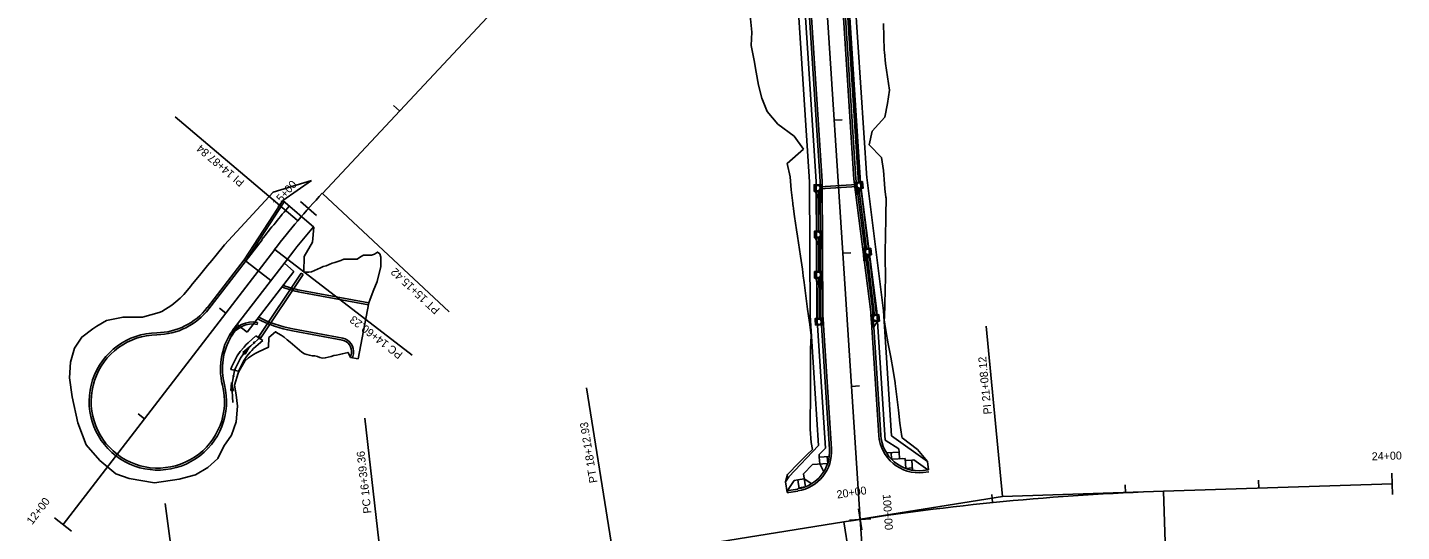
# Model space of a CAD drawing. Extents: x 979959 to 994833, y 1835619 to 1845316.
# Drawn here: x 982028 to 983058, y 1842647 to 1843025 of the extents above; entities that cross this region are included whole.
import ezdxf

# ---------------------------------------------------------------- set-up
doc = ezdxf.new("R2010")
doc.units = 0
for name, color, linetype in [('R_Drainage', 7, 'Continuous'), ('R_Horz Alg', 7, 'Continuous'), ('R_Horz Alg Annot', 7, 'Continuous'), ('R_Horz Alg Annot_Side Road', 7, 'Continuous'), ('R_Horz Alg Stationing', 7, 'Continuous'), ('R_Horz Alg Stationing_Side Road', 7, 'Continuous'), ('R_Proposed Const Limits', 7, 'Continuous'), ('R_Proposed Road', 7, 'Continuous'), ('R_Special Ditch', 7, 'Continuous')]:
    doc.layers.add(name, color=color, linetype=linetype)

msp = doc.modelspace()

# ---------------------------------------------------------------- linework, layer by layer
at = {"layer": 'R_Drainage'}
for p, q in [((982651.3, 1842908.5), (982637.8, 1843118.6)), ((982652.8, 1842908.6), (982639.3, 1843118.7)), ((982618.1, 1842902.1), (982618.1, 1842907.1)), ((982622.7, 1842894.2), (982618.3, 1842903.6)), ((982620, 1842871.5), (982619.9, 1842902.8)), ((982621.5, 1842871.5), (982621.4, 1842902.8)), ((982622.4, 1842905.5), (982650.2, 1842907.3)), ((982622.5, 1842904), (982650.3, 1842905.9)), ((982623.2, 1842894.2), (982623.1, 1842907.2)), ((982649.4, 1842908.9), (982650.5, 1842900)), ((982651, 1842900), (982654.3, 1842905.4)), ((982657.4, 1842858.6), (982651.6, 1842904.8)), ((982658.9, 1842858.8), (982653.1, 1842905)), ((982654.3, 1842909.5), (982654.9, 1842904.6)), ((982618.3, 1842867.2), (982618.3, 1842872.2)), ((982623.4, 1842859.2), (982623.3, 1842872.2)), ((982622.9, 1842859.2), (982618.5, 1842868.6)), ((982620.2, 1842841.4), (982620.1, 1842867.8)), ((982621.7, 1842841.4), (982621.6, 1842867.8)), ((982655.8, 1842859.2), (982656.3, 1842850.3)), ((982656.8, 1842850.3), (982660.5, 1842855.5)), ((982663.4, 1842808.9), (982657.9, 1842855)), ((982664.9, 1842809.1), (982659.4, 1842855.1)), ((982660.7, 1842859.6), (982661.1, 1842854.6)), ((982201.4, 1842792.6), (982233.5, 1842840.9)), ((982235.2, 1842839.8), (982233.5, 1842840.9)), ((982618.5, 1842837), (982618.4, 1842842)), ((982623.5, 1842829.1), (982623.4, 1842842.1)), ((982203, 1842791.5), (982235.2, 1842839.8)), ((982623, 1842829.1), (982618.7, 1842838.5)), ((982620.7, 1842806.2), (982620.2, 1842837.7)), ((982622.2, 1842806.2), (982621.7, 1842837.7)), ((982661.7, 1842809.5), (982662.3, 1842800.5)), ((982666.7, 1842809.8), (982667, 1842804.9)), ((982619.1, 1842801.7), (982618.8, 1842806.7)), ((982662.8, 1842800.6), (982666.4, 1842805.8)), ((982203, 1842791.5), (982201.4, 1842792.6))]:
    msp.add_line(p, q, dxfattribs=at)
for points in [[(982618.1, 1842902.1), (982618.1, 1842907.1), (982623.1, 1842907.2), (982623.1, 1842902.2)], [(982622.7, 1842894.2), (982622.6, 1842907.2), (982624.1, 1842907.2), (982624.2, 1842894.2)], [(982649.8, 1842909), (982651, 1842900), (982649.5, 1842899.8), (982648.4, 1842908.8)], [(982654.3, 1842909.5), (982654.9, 1842904.6), (982650, 1842903.9), (982649.4, 1842908.9)], [(982618.3, 1842867.2), (982618.3, 1842872.2), (982623.3, 1842872.2), (982623.3, 1842867.2)], [(982622.9, 1842859.2), (982622.8, 1842872.2), (982624.3, 1842872.2), (982624.4, 1842859.2)], [(982656.3, 1842859.3), (982656.8, 1842850.3), (982655.3, 1842850.2), (982654.8, 1842859.2)], [(982660.7, 1842859.6), (982661.1, 1842854.6), (982656.1, 1842854.2), (982655.8, 1842859.2)], [(982618.5, 1842837), (982618.4, 1842842), (982623.4, 1842842.1), (982623.5, 1842837.1)], [(982623, 1842829.1), (982622.9, 1842842.1), (982624.4, 1842842.1), (982624.5, 1842829.1)], [(982662.2, 1842809.6), (982662.8, 1842800.6), (982661.3, 1842800.5), (982660.7, 1842809.5)], [(982666.7, 1842809.8), (982667, 1842804.9), (982662, 1842804.5), (982661.7, 1842809.5)], [(982619.1, 1842801.7), (982618.8, 1842806.7), (982623.8, 1842807), (982624.1, 1842802.1)], [(982623.6, 1842802), (982623.3, 1842807), (982624.8, 1842807.1), (982625.1, 1842802.1)]]:
    msp.add_lwpolyline(points, close=True, dxfattribs=at)
for centre, radius in [((982620.6, 1842904.7), 2.5), ((982620.6, 1842904.7), 2.5), ((982620.6, 1842904.7), 2), ((982620.6, 1842904.7), 2), ((982652.1, 1842906.7), 2.5), ((982652.1, 1842906.7), 2.5), ((982652.1, 1842906.7), 2), ((982652.1, 1842906.7), 2), ((982620.8, 1842869.7), 2.5), ((982620.8, 1842869.7), 2.5), ((982620.8, 1842869.7), 2), ((982620.8, 1842869.7), 2), ((982658.4, 1842856.9), 2.5), ((982658.4, 1842856.9), 2.5), ((982658.4, 1842856.9), 2), ((982658.4, 1842856.9), 2), ((982621, 1842839.5), 2.5), ((982621, 1842839.5), 2.5), ((982621, 1842839.5), 2), ((982621, 1842839.5), 2), ((982664.4, 1842807.2), 2.5), ((982664.4, 1842807.2), 2.5), ((982664.4, 1842807.2), 2), ((982664.4, 1842807.2), 2), ((982621.5, 1842804.4), 2.5), ((982621.5, 1842804.4), 2.5), ((982621.5, 1842804.4), 2), ((982621.5, 1842804.4), 2)]:
    msp.add_circle(centre, radius, dxfattribs=at)
at = {"layer": 'R_Horz Alg'}
for p, q in [((982249.5, 1842900.7), (982462.4, 1843128.4)), ((982622.6, 1843116.2), (982652.7, 1842656.1)), ((982055.2, 1842652.3), (982213.8, 1842858.6)), ((982880, 1842677.2), (983051.5, 1842682.9)), ((982652.7, 1842656.1), (982665.3, 1842462.2)), ((982468, 1842626.5), (982640.3, 1842654.2))]:
    msp.add_line(p, q, dxfattribs=at)
for centre, radius, start, end in [((982668, 1842509.4), 573, 136.9251, 142.4445), ((982942.7, 1840768.4), 1909.9, 91.8826, 99.1106)]:
    msp.add_arc(centre, radius, start, end, dxfattribs=at)
at = {"layer": 'R_Horz Alg Annot'}
for points in [[(982230.6, 1842880.5), (982139.1, 1842958.1)], [(982249.5, 1842900.7), (982344.5, 1842811.9)], [(982213.8, 1842858.6), (982316.9, 1842779.4)]]:
    msp.add_lwpolyline(points, dxfattribs=at)
at = {"layer": 'R_Horz Alg Annot_Side Road'}
for p, q in [((982759.4, 1842673.3), (982880, 1842677.2)), ((982640.3, 1842654.2), (982759.4, 1842673.3))]:
    msp.add_line(p, q, dxfattribs=at)
for points in [[(982759.4, 1842673.3), (982747.1, 1842801.1)], [(982468, 1842626.5), (982447.4, 1842754.9)], [(982296, 1842602.9), (982281.3, 1842732.1)], [(982880, 1842677.2), (982884.3, 1842547.3)], [(982142.8, 1842585.5), (982131.7, 1842668.1)], [(982640.3, 1842654.2), (982651.6, 1842583.8)]]:
    msp.add_lwpolyline(points, dxfattribs=at)
at = {"layer": 'R_Horz Alg Stationing'}
for points in [[(982302.9, 1842966.6), (982307.3, 1842962.5)], [(982639.1, 1842955.9), (982633.1, 1842955.5)], [(982233.1, 1842894.6), (982245.1, 1842884)], [(982645.6, 1842856.1), (982639.6, 1842855.7)], [(982172.3, 1842814.5), (982177.1, 1842810.9)], [(982652.2, 1842756.3), (982646.2, 1842755.9)], [(982111.4, 1842735.2), (982116.1, 1842731.6)], [(983051.2, 1842690.9), (983051.7, 1842674.9)], [(982048.8, 1842657.2), (982061.5, 1842647.4)], [(982660.7, 1842656.6), (982644.7, 1842655.6)], [(982651.5, 1842664), (982653.9, 1842648.2)]]:
    msp.add_lwpolyline(points, dxfattribs=at)
at = {"layer": 'R_Horz Alg Stationing_Side Road'}
for points in [[(982951.3, 1842685.6), (982951.5, 1842679.6)], [(982851.3, 1842682.1), (982851.6, 1842676.1)], [(982751.3, 1842674.7), (982751.9, 1842668.7)]]:
    msp.add_lwpolyline(points, dxfattribs=at)
at = {"layer": 'R_Proposed Const Limits'}
for points in [[(982566.3, 1843061.3), (982568.8, 1843051.5), (982568.2, 1843041.4), (982569.7, 1843037.6), (982570.5, 1843031.5), (982571.5, 1843021.6), (982570.9, 1843011.5), (982572.8, 1843001.6), (982573.1, 1843000.3), (982574.6, 1842991.7), (982576.4, 1842981.8), (982578.8, 1842972), (982582.8, 1842962.2), (982590.8, 1842952.7), (982603.1, 1842943.5), (982610.1, 1842933.9)], [(982670, 1843028), (982670.4, 1843018), (982670.7, 1843008), (982670.8, 1843006.7), (982671.6, 1842998.1), (982673.1, 1842988.1), (982674.7, 1842978.2), (982673.1, 1842968.1), (982671, 1842957.9), (982661.6, 1842947.3), (982659.3, 1842937.1)], [(982670, 1843028), (982670.4, 1843018), (982670.7, 1843008), (982670.8, 1843006.7), (982671.6, 1842998.1), (982673.1, 1842988.1), (982674.7, 1842978.2), (982673.1, 1842968.1), (982671, 1842957.9), (982661.6, 1842947.3), (982659.3, 1842937.1)], [(982610.1, 1842933.9), (982598, 1842923.1), (982600.2, 1842913.2), (982600.9, 1842903.3), (982601.3, 1842899.4), (982602.1, 1842893.3), (982602.2, 1842892.6), (982602.4, 1842890.8), (982602.6, 1842889.9), (982602.6, 1842889.5), (982602.7, 1842889), (982603.4, 1842883.4), (982604.9, 1842873.4), (982605.7, 1842868.5), (982606.4, 1842863.5), (982607.9, 1842853.6), (982607.9, 1842853.6), (982609.3, 1842843.7), (982610, 1842838.7), (982610.7, 1842833.7), (982611.9, 1842823.8), (982613.1, 1842813.9), (982614.6, 1842803.9), (982614.9, 1842802.3), (982615.9, 1842794)], [(982659.3, 1842937.1), (982668.5, 1842927.7), (982670, 1842917.8), (982670.8, 1842907.8), (982671.2, 1842904), (982671.9, 1842897.9), (982672, 1842897.1), (982672, 1842895.4), (982672, 1842894.4), (982672, 1842894), (982672, 1842893.5), (982671.9, 1842887.8), (982671.8, 1842877.8), (982671.7, 1842872.8), (982671.6, 1842867.8), (982671.3, 1842857.7), (982671.3, 1842857.7), (982671.4, 1842847.7), (982671.5, 1842842.7), (982671.5, 1842837.7), (982671.4, 1842827.7), (982671.2, 1842817.7), (982670.8, 1842807.6), (982670.7, 1842805.9)], [(982127.3, 1842811.3), (982129.1, 1842812.1), (982136.6, 1842816.8), (982139.6, 1842819.3), (982142.9, 1842822), (982144.3, 1842823.4), (982145.7, 1842824.9), (982150.8, 1842831.1), (982151.2, 1842831.6), (982157.1, 1842838.8), (982157.4, 1842839.1), (982163.5, 1842846.5), (982166.7, 1842850.4), (982169.8, 1842854.3), (982176.2, 1842862), (982212.6, 1842901.5), (982241.4, 1842910.4)], [(982235.5, 1842841.9), (982235.9, 1842853.4), (982242.2, 1842864.1), (982243, 1842875.4)], [(982235.5, 1842841.8), (982237.2, 1842841.6), (982239.3, 1842841.6), (982241.3, 1842841.8), (982243.6, 1842842.8), (982245.8, 1842843.8), (982248, 1842844.8), (982250.2, 1842845.8), (982252.4, 1842846.3), (982254.6, 1842847.4), (982256.8, 1842848.2), (982258.9, 1842848.9), (982261.1, 1842849.6), (982263.3, 1842850.4), (982265.5, 1842851.2), (982267.5, 1842851.2), (982269.6, 1842851.3), (982271.6, 1842851.3), (982273.6, 1842851.4), (982275.7, 1842851.4), (982278, 1842853), (982280.3, 1842854.3), (982282.3, 1842854.3), (982284.3, 1842854.2), (982286.4, 1842854.2), (982288.6, 1842855), (982290.9, 1842856.6), (982292.5, 1842855.4)], [(982292.5, 1842855.4), (982293.4, 1842852.9), (982293.4, 1842845.9), (982290.6, 1842834.5), (982287.6, 1842827.4), (982284.3, 1842818.5)], [(982104.6, 1842686.9), (982094.8, 1842690.2), (982082.7, 1842700.4), (982072.4, 1842712), (982066.1, 1842728.6), (982062, 1842748), (982059.9, 1842762.2), (982060.8, 1842774.1), (982063.7, 1842784.5), (982069.2, 1842792.9), (982077.5, 1842799.1), (982080.5, 1842801), (982087.6, 1842805.4), (982100.2, 1842807.9), (982114.8, 1842807.9), (982127.3, 1842811.3)], [(982670.7, 1842805.9), (982671.9, 1842797.7), (982673.7, 1842787.8), (982675.6, 1842777.9), (982677.3, 1842767.9), (982678.8, 1842758.6), (982678.9, 1842758), (982680, 1842748.1), (982681.3, 1842738.1), (982682.4, 1842728.2), (982683.8, 1842718.3), (982684.2, 1842717.2), (982695.7, 1842708.5), (982703.1, 1842699.5)], [(982184.9, 1842749.5), (982183.6, 1842756.8), (982186.4, 1842765.9), (982187.1, 1842767.5), (982191.3, 1842774.7), (982194.1, 1842777.4), (982197.8, 1842779.8), (982199.7, 1842780.8), (982201.7, 1842781.9), (982209.2, 1842785.4), (982209.3, 1842792.6)], [(982209.2, 1842785.4), (982209.3, 1842792.6)], [(982209.3, 1842792.6), (982214.3, 1842796.9), (982216.5, 1842795.6), (982218.7, 1842794.2), (982220.9, 1842792.8), (982223.1, 1842790.9), (982225.4, 1842789), (982227.2, 1842787.6), (982228.9, 1842786.1), (982230.7, 1842784.6), (982232.4, 1842783), (982234.2, 1842781.5), (982236, 1842780.2), (982237.9, 1842779.7), (982239.8, 1842779.2), (982241.8, 1842778.9), (982243.8, 1842778.7), (982245.8, 1842778.2), (982247.7, 1842777.6), (982249.6, 1842777.1), (982251.7, 1842777.2), (982253.8, 1842777.8), (982256, 1842778.4), (982258.1, 1842779), (982260.2, 1842779.4), (982262.3, 1842779.8), (982264.4, 1842780.2), (982266.6, 1842780.7), (982268.8, 1842781.4), (982270.7, 1842777.5)], [(982615.9, 1842794), (982615.5, 1842784), (982615.3, 1842773.9), (982615.3, 1842763.9), (982615.3, 1842754.4), (982615.3, 1842753.9), (982615.3, 1842743.9), (982615.1, 1842733.8), (982615.1, 1842723.8), (982616, 1842713.8), (982616.8, 1842708.5), (982612.8, 1842704.7), (982606.6, 1842698.5), (982598.1, 1842689.9), (982596.7, 1842684.4)], [(982175.7, 1842711), (982181.5, 1842719.2), (982181.5, 1842719.2), (982184.8, 1842729.2), (982186, 1842741), (982184.9, 1842749.5)], [(982104.6, 1842686.9), (982123.8, 1842683.6), (982142.1, 1842686.4), (982154.3, 1842689.6), (982163.7, 1842695), (982171.2, 1842701.9), (982175.7, 1842711)]]:
    msp.add_lwpolyline(points, dxfattribs=at)
at = {"layer": 'R_Proposed Road'}
for p, q in [((982601.2, 1843114.8), (982614.6, 1842909.4)), ((982606.2, 1843115.2), (982619.6, 1842909.6)), ((982609.2, 1843115.4), (982622.6, 1842909.7)), ((982610.7, 1843115.5), (982624.1, 1842909.8)), ((982634.6, 1843117), (982648, 1842911.3)), ((982636.1, 1843117.1), (982649.5, 1842911.5)), ((982639.1, 1843117.3), (982652.5, 1842911.8)), ((982644.1, 1843117.6), (982657.5, 1842912.2)), ((982657.5, 1842912.5), (982670, 1842812.6)), ((982219.8, 1842895.3), (982241.4, 1842910.4)), ((982614.6, 1842909.7), (982615.1, 1842809)), ((982619.6, 1842909.8), (982620.1, 1842809.3)), ((982622.6, 1842909.8), (982623.1, 1842809.5)), ((982624.1, 1842909.8), (982624.6, 1842809.6)), ((982648, 1842911.3), (982660.5, 1842811.9)), ((982649.5, 1842911.5), (982662, 1842812)), ((982652.5, 1842911.9), (982665, 1842812.2)), ((982219.8, 1842895.3), (982190.8, 1842850.8)), ((982221, 1842894.4), (982192, 1842849.9)), ((982219.8, 1842895.3), (982243, 1842875.4)), ((982164.5, 1842814.1), (982204.3, 1842865.9)), ((982163.3, 1842815.1), (982190.8, 1842850.8)), ((982183.5, 1842799.5), (982223.3, 1842851.3)), ((982211, 1842835.3), (982190.8, 1842850.8)), ((982193.1, 1842796.5), (982228.2, 1842842.1)), ((982228.2, 1842842.1), (982221.1, 1842848.4)), ((982232.5, 1842826.6), (982284, 1842817)), ((982232.7, 1842828.1), (982284.3, 1842818.5)), ((982284.3, 1842818.5), (982276.4, 1842776.5)), ((982620.1, 1842809.3), (982626.6, 1842709.6)), ((982623.1, 1842809.5), (982629.7, 1842708.9)), ((982624.6, 1842809.6), (982631.2, 1842709)), ((982660.5, 1842811.9), (982666.6, 1842719.1)), ((982662, 1842812), (982668.1, 1842719.2)), ((982665, 1842812.2), (982671.3, 1842715.5)), ((982670, 1842812.6), (982676.1, 1842718.9)), ((982183.5, 1842799.5), (982185.6, 1842802.3)), ((982184.7, 1842798.6), (982186.8, 1842801.3)), ((982193.1, 1842796.5), (982185.6, 1842802.3)), ((982200.6, 1842802.4), (982200.9, 1842803.9)), ((982227.3, 1842799.1), (982264.8, 1842792.1)), ((982615.1, 1842809), (982621.5, 1842711.5)), ((982227.1, 1842797.6), (982264.5, 1842790.6)), ((982271.3, 1842780.7), (982270.7, 1842777.5)), ((982272.8, 1842780.4), (982272.2, 1842777.3)), ((982270.7, 1842777.5), (982276.4, 1842776.5)), ((982676.1, 1842718.9), (982703.1, 1842699.5)), ((982621.5, 1842711.5), (982599.1, 1842688)), ((982626.6, 1842709.6), (982621.9, 1842704.7)), ((982671.3, 1842715.5), (982681.6, 1842709.1)), ((982675.8, 1842706.2), (982676.1, 1842701.2)), ((982681.6, 1842709.1), (982681.8, 1842706.6)), ((982681.8, 1842706.6), (982682.1, 1842701.6)), ((982616.9, 1842697.4), (982610.1, 1842690.2)), ((982616.9, 1842697.4), (982628.3, 1842698.1)), ((982622, 1842702.7), (982621.9, 1842704.7)), ((982622.3, 1842697.7), (982622, 1842702.7)), ((982622.3, 1842697.7), (982625.4, 1842691.9)), ((982628.3, 1842698.1), (982628, 1842703.1)), ((982684.3, 1842701.8), (982682.1, 1842701.6)), ((982686.3, 1842701.9), (982686.8, 1842694.3)), ((982691.4, 1842700.6), (982686.3, 1842700.3)), ((982692.9, 1842700.7), (982691.4, 1842700.6)), ((982691.4, 1842700.6), (982691.9, 1842693)), ((982692.9, 1842700.7), (982703.3, 1842693.2)), ((982703.8, 1842693.2), (982703.1, 1842699.5)), ((982599.1, 1842688), (982596.7, 1842684.4)), ((982603.2, 1842685.3), (982605.8, 1842685.7)), ((982605.8, 1842685.7), (982610.7, 1842686.5)), ((982606.8, 1842679.1), (982605.8, 1842685.7)), ((982611.7, 1842680.5), (982610.1, 1842690.2)), ((982610.7, 1842686.5), (982616.4, 1842682.9)), ((982691.7, 1842694.7), (982686.8, 1842694.3)), ((982703.8, 1842693.2), (982699.7, 1842692.8)), ((982704, 1842691.7), (982699.9, 1842691.3)), ((982598, 1842676.2), (982596.7, 1842684.4)), ((982597.8, 1842677.6), (982599, 1842677.8)), ((982598, 1842676.2), (982599.2, 1842676.4)), ((982603.2, 1842685.3), (982598.2, 1842677.7)), ((982599, 1842677.8), (982605.8, 1842678.9)), ((982599.2, 1842676.4), (982606, 1842677.4)), ((982606.7, 1842679.8), (982611.7, 1842680.5))]:
    msp.add_line(p, q, dxfattribs=at)
for points in [[(982681.8, 1842706.6), (982672.4, 1842706)], [(982629.5, 1842703.2), (982622, 1842702.7)], [(982686.3, 1842701.9), (982676.1, 1842701.2)]]:
    msp.add_lwpolyline(points, dxfattribs=at)
for centre, radius, start, end in [((982668, 1842509.4), 585, 139.267, 142.4445), ((982668, 1842509.4), 561, 139.267, 142.4445), ((982244.5, 1842891.5), 66, 247.5155, 259.4497), ((982244.5, 1842891.5), 64.5, 247.8747, 259.4497), ((982124.8, 1842844.6), 48.5, 270.7606, 322.4445), ((982124.8, 1842844.6), 50, 270.7606, 322.4445), ((982223.1, 1842769), 50, 142.4445, 194.1283), ((982197.3, 1842784.2), 20, 79.4497, 149.6432), ((982223.1, 1842769), 50, 142.4445, 149.6432), ((982197.3, 1842784.2), 18.5, 79.4497, 149.6432), ((982244.5, 1842891.5), 95.5, 242.7966, 259.4497), ((982244.5, 1842891.5), 94, 242.9637, 259.4497), ((982126.2, 1842744.6), 51.5, 90.7606, 14.1283), ((982126.2, 1842744.6), 50, 90.7606, 14.1283), ((982223.1, 1842769), 48.5, 149.6432, 194.1283), ((982223.1, 1842769), 48.5, 142.4445, 149.6432), ((982262.9, 1842782.2), 8.5, 349.4497, 79.4497), ((982262.9, 1842782.2), 10, 349.4497, 79.4497), ((982696.5, 1842721.1), 30, 183.7353, 276.4349), ((982696.5, 1842721.1), 28.5, 183.7353, 276.4349), ((982601.2, 1842707.1), 28.5, 279.1275, 3.7353), ((982601.2, 1842707.1), 30, 279.1275, 3.7353)]:
    msp.add_arc(centre, radius, start, end, dxfattribs=at)
at = {"layer": 'R_Special Ditch'}
for p, q in [((982204.8, 1842790.3), (982199.6, 1842793.7)), ((982194.6, 1842785.3), (982189.9, 1842781.4)), ((982189.9, 1842781.4), (982191.6, 1842780)), ((982191.6, 1842780), (982194.6, 1842785.3)), ((982186.7, 1842767.4), (982180.8, 1842768.5)), ((982181.5, 1842758.7), (982180.8, 1842752.7)), ((982182.9, 1842752.8), (982181.5, 1842758.7)), ((982180.8, 1842752.7), (982182.9, 1842752.8))]:
    msp.add_line(p, q, dxfattribs=at)
for points in [[(982180.8, 1842768.5), (982180.8, 1842768.7), (982181.6, 1842770.8), (982185.6, 1842778.7), (982188, 1842782.1), (982190.8, 1842785.4), (982192.2, 1842787), (982193.8, 1842788.6), (982199.6, 1842793.7)], [(982182.4, 1842743.7), (982181.6, 1842756.9), (982183.7, 1842767.9), (982184.4, 1842769.6), (982188.2, 1842777.1), (982190.4, 1842780.3), (982193, 1842783.5), (982194.4, 1842785), (982195.8, 1842786.4), (982203.7, 1842793.3)], [(982186.7, 1842767.4), (982187.1, 1842768.4), (982190.8, 1842775.6), (982192.8, 1842778.5), (982195.3, 1842781.5), (982196.6, 1842782.9), (982197.9, 1842784.2), (982204.8, 1842790.3)], [(982186.1, 1842773), (982188.2, 1842777.1), (982190.4, 1842780.3), (982193, 1842783.5), (982194.4, 1842785), (982194.7, 1842785.2)], [(982186.1, 1842773), (982186.1, 1842773)], [(982182.4, 1842743.7), (982181.6, 1842756.9), (982182, 1842758.7)]]:
    msp.add_lwpolyline(points, dxfattribs=at)
for centre in [(982198.3, 1842788.7), (982202.1, 1842792), (982183.9, 1842768.5), (982182.9, 1842763.6)]:
    msp.add_circle(centre, 0.375, dxfattribs=at)

# ---------------------------------------------------------------- texts
at = {"layer": 'R_Horz Alg Annot'}
for s, rotation, p in [('PI 14+87.84', 139.6848, (982191.6, 1842909.7)), ('PT 15+15.42', 136.9251, (982338, 1842813.8)), ('PC 14+60.23', 142.4445, (982310.3, 1842780.7)), ('PI 21+08.12', 95.4966, (982751.2, 1842735.2)), ('PT 18+12.93', 99.1106, (982455.7, 1842683.9)), ('PC 16+39.36', 96.507, (982286.4, 1842660.9))]:
    msp.add_text(s, height=6, rotation=rotation, dxfattribs=at).set_placement(p)
at = {"layer": 'R_Horz Alg Stationing'}
for s, rotation, p in [('15+00', 48.467, (982215.9, 1842890.2)), ('24+00', 1.8826, (983036.2, 1842700.4)), ('20+00', 8.7353, (982635.5, 1842671.7)), ('12+00', 52.4445, (982032, 1842651.7)), ('100+00', 273.7353, (982669.5, 1842674.9))]:
    msp.add_text(s, height=6, rotation=rotation, dxfattribs=at).set_placement(p)

doc.saveas('drawing.dxf')
